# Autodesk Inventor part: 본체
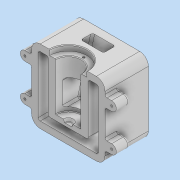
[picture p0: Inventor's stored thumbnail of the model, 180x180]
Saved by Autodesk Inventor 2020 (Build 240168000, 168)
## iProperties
Created: 2022-03
Part Number: 본체
Material: 일반
Document SubType Name: Modeling
Designer: Administrator
Density: 1 g/cm^3
Appearance: 기본값
Author: Administrator
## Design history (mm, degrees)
sketch "스케치1"
  geometry: L1 (-55, -55)-(55, -55); L2 (55, -55)-(55, 55); L3 (55, 55)-(-55, 55); L4 (-55, 55)-(-55, -55); L5 (-55, -55)-(55, 55); L6 (55, -55)-(-55, 55); 1 further point
  constraints: 12 end point, 2 midpoint, 2 parallel, 1 horizontal, 1 perpendicular
  dimensions: "d0" = 110 distance of L2.end L3.end; "d1" = 110 distance of L1.end L2.end
extrude "돌출1" new body sketch "스케치1" distance "d2" = 65; taper "d3" = 0 deg
node "작업 평면1"
sketch "스케치2"
  geometry: L1 (45, 45)-(45, -45); L2 (45, -45)-(-45, -45); L3 (-45, -45)-(-45, 45); L4 (-45, 45)-(-30, 45); L5 (-30, 45)-(-30, -33); L6 (-30, -33)-(30, -33); L7 (30, -33)-(30, 45); L8 (30, 45)-(45, 45); L9 (-55, -55)-(55, -55) reference; L10 (55, -55)-(55, 55) reference; L11 (-55, 55)-(-55, -55) reference; L12 (55, 55)-(-55, 55) reference; 1 further point
  constraints: 16 end point, 5 perpendicular, 2 vertical, 1 horizontal
  dimensions: "d5" = 10 distance between parallel lines of L2 L9; "d6" = 22 distance between parallel lines of L6 L9; "d7" = 10 distance between parallel lines of L1 L10; "d8" = 25 distance between parallel lines of L7 L10; "d9" = 10 distance between parallel lines of L3 L11; "d10" = 25 distance between parallel lines of L5 L11; "d11" = 10 distance between parallel lines of L4 L12; "d12" = 10 distance between parallel lines of L8 L12
extrude "돌출2" cut sketch "스케치2" distance "d13" = 104.5; taper "d14" = 0 deg
sketch "스케치3"
  geometry: L1 (-30, 22)-(-9.1, 100); L2 (-65, 100)-(0, 100) reference; L3 (0, 100)-(0, 22) reference; L4 (-65, 22)-(0, 22) reference; 1 further point
  constraints: 2 end point, 2 point on line
  dimensions: "d15" = 75 deg angle of L4 L1; "d16" = 30 horizontal distance of point (0, 55) L1.start
extrude "돌출3" cut sketch "스케치3" distance "d17" = 80; taper "d18" = 0 deg
sketch "스케치4"
  geometry: L1 (110, -65)-(0, -65) reference; 3 further points
  constraints: 1 coincident, 1 midpoint
hole "구멍1" sketch "스케치4" at (55, -65) diameter "d19" = 38; stored, may be unused: countersink angle "d23" = 90 deg, drill point angle "d25" = 0 deg; dims "d20" = 8, "d21" = 56, "d22" = 8, "d24" = 80
sketch "스케치5"
  geometry: L1 (19, 0)-(-19, 0) reference; C1 r 7.5 at (0, 0); 2 further points
  constraints: 1 centre point, 1 coincident, 1 midpoint
  dimensions: "d26" = 15 diameter of C1
extrude "돌출4" new body sketch "스케치5" distance "d27" = 4; taper "d28" = 0 deg
feature "면 기울기1" dims angle "d29" = -30 deg
feature "결합1"
  node "솔리드2"
sketch "스케치8"
  geometry: L1 (45, 9.1)-(-33, 30) reference; L2 (55, 11.597)-(-19, 31.425); L3 (55, 29.197)-(-19, 49.025); L4 (55, 0)-(55, 65) reference; L5 (-19, 49.025)-(-19, 31.425); 1 further point
  constraints: 6 end point, 2 parallel, 2 point on line, 1 vertical
  dimensions: "d39" = 5 distance between parallel lines of L1 L2; "d40" = 17 distance between parallel lines of L2 L3; "d41" = 74 distance between parallel lines of L5 L4
extrude "돌출7" cut sketch "스케치8" stored distance "d42" = 34; taper "d43" = 0 deg
sketch "스케치9"
  geometry: L1 (17, -19)-(-17, -19); L2 (-17, -19)-(-17, 19); L3 (-17, 19)-(17, 19); L4 (17, 19)-(17, -19); L5 (-28, 55)-(-55, 55) reference; 2 further points
  constraints: 8 end point, 2 parallel, 1 horizontal, 1 midpoint, 1 perpendicular, 1 vertical alignment
  dimensions: "d44" = 34 distance of L2.end L3.end; "d45" = 36 distance between parallel lines of L3 L5; "d46" = 38 distance of L1.end L2.end
extrude "돌출8" cut sketch "스케치9" stored distance "d47" = 34; taper "d48" = 0 deg
sketch "스케치10"
  geometry: L1 (-55, -55)-(55, -55) reference; L2 (65, -35)-(45, -35); L3 (65, -21)-(45, -21); L4 (45, 45)-(45, -45) reference; L5 (65, 21)-(45, 21); L6 (65, 35)-(45, 35); L7 (0, 0)-(0, 78.566); L8 (-65, -35)-(-45, -35); L9 (-65, -21)-(-45, -21); L10 (-65, 21)-(-45, 21); L11 (-65, 35)-(-45, 35); L12 (-45, -45)-(-45, 45) reference; A1 r 7 centre (65, -28) between (65, -35) and (65, -21); A2 r 7 centre (65, 28) between (65, 21) and (65, 35); A3 r 7 centre (-65, -28) between (-65, -21) and (-65, -35); A4 r 7 centre (-65, 28) between (-65, 35) and (-65, 21)
  constraints: 18 end point, 10 symmetric about line, 8 point on circle, 4 centre point, 4 point on line, 4 tangent, 3 horizontal, 1 equal radius, 1 perpendicular, 1 vertical, 1 vertical alignment, 2 other
  dimensions: "d49" = 14 diameter of A1; "d50" = 27 distance from line of A1.centre L1; "d51" = 56 distance of A2.centre A1.centre; "d52" = 65 horizontal distance of L7.start A1.centre
extrude "돌출9" join sketch "스케치10" distance "d53" = 20; taper "d54" = 0 deg
sketch "스케치11"
  geometry: A1 r 28 centre (0, 0) between (28, 0) and (-28, 0) reference; 2 further points
  constraints: 1 vertical alignment
  dimensions: "d55" = 23 distance of A1.centre point (0, 23)
hole "구멍2" sketch "스케치11" at (0, 23) diameter "d56" = 3.242; stored, may be unused: countersink angle "d60" = 90 deg, drill point angle "d62" = 118 deg; dims "d57" = 9, "d58" = 56, "d59" = 8, "d61" = 11
sketch "스케치12"
  geometry: A1 r 7 centre (65, -28) between (65, -35) and (65, -21) reference; A2 r 7 centre (65, 28) between (65, 21) and (65, 35) reference; A3 r 7 centre (-65, 28) between (-65, 35) and (-65, 21) reference; A4 r 7 centre (-65, -28) between (-65, -21) and (-65, -35) reference; 5 further points
  constraints: 4 coincident
hole "구멍3" sketch "스케치12" at (65, -28), (65, 28), (-65, 28), (-65, -28) diameter "d63" = 3.242; stored, may be unused: countersink angle "d67" = 90 deg, drill point angle "d69" = 118 deg; dims "d64" = 9, "d65" = 56, "d66" = 8, "d68" = 11
fillet "모깎기1" dims "d70" = 1
fillet "모깎기2" dims "d71" = 1
fillet "모깎기3" dims "d72" = 3
fillet "모깎기4" dims "d73" = 13
fillet "모깎기5" dims "d74" = 3
fillet "모깎기6" dims "d75" = 3
fillet "모깎기7" dims "d76" = 3
chamfer "모따기1" distance "d77" = 1; stored, may be unused: second distance "d78" = 2, angle "d79" = 45 deg
sketch "스케치13"
  geometry: L1 (-65, 60)-(-65, -24) reference; L2 (0, 73)-(-65, 73) reference; 2 further points
  constraints: 1 other
  dimensions: "d80" = 20 distance from line of point (-45, 18) L1; "d81" = 55 distance from line of point (-45, 18) L2
feature "엠보싱1" sketch "스케치13" dims "d0" = 110, "d1" = 110, "d82" = 0.5, "d83" = 0
fillet "모깎기8" dims "d84" = 3
node "솔리드1"
feature "A9D066F2-1C7D-4E18-AEED-F7BC21143FA4" dims "d19" = 38, "d20" = 8, "d21" = 56, "d22" = 8, "d23" = 90 deg, "d24" = 80, "d25" = 0
